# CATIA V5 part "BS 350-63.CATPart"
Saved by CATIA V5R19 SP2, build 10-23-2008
Part number: BS 300-63
Bounding box of the stored display mesh (mm): x -15.868 to 15.868, y -15.868 to 15.868, z 0 to 156
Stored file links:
  C:\Users\Bora\Desktop\3D Katı model\BS serisi\BS 300\BS 300-63.CATPart
  C:\Program Files\Dassault Systemes\B19\intel_a\reffiles\standard\MetricThickPitch.txt
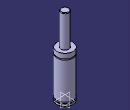
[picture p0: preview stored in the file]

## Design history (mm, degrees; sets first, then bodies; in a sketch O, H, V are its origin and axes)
Body1 (main body)
  Sketch1 on yz-plane, origin (0, 0, 0), H (0, 1, 0), V (0, 0, 1)
    point P1 (8, 155)
    point P3 (8, 155)
    point P5 (16, 82.5)
    point P6 (16, 80.5)
    point P9 (16, 82.5)
    point P14 (16, 80.5)
    line L1 (8, 155) -> (8, 92)
    arc A1 centre (7, 155) radius 1 from (8, 155) to (7, 156) ccw
    arc A2 centre (16, 81.5) radius 1 from (16, 82.5) to (16, 80.5) ccw
    line L2 (16, 0) -> (16, 4)
    line L3 (16, 82.5) -> (16, 92)
    line L4 (14.5, 7.5) -> (14.5, 4)
    line L5 (16, 7.5) -> (16, 80.5)
    line L6 (7, 156) -> (0, 156)
    point P15 (0, 156)
    line L7 (8, 92) -> (16, 92)
    line L8 (0, 0) -> (16, 0)
    line L9 (14.5, 7.5) -> (16, 7.5)
    line L10 (14.5, 4) -> (16, 4)
    coincidence: P15 V, P1 P3, P5 P9, P6 P14
    tangency: L6 A1
    horizontal: L7 H, L8 H, L9 H, L10 H
  Shaft1: profile Sketch1, axis Sketch1.V, angle 360
  Sketch2 on face of Shaft1 from Sketch1.L8, origin (0, 0, 0), H (1, 0, 0), V (0, -1, 0)
    point P1 (0, 0)
  Hole1: placed by Sketch2, at (0, 0, 0) direction (0, 0, 1), diameter 6.647, depth 4, threaded "M8", thread diameter 8, thread depth 4, pitch 1.25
